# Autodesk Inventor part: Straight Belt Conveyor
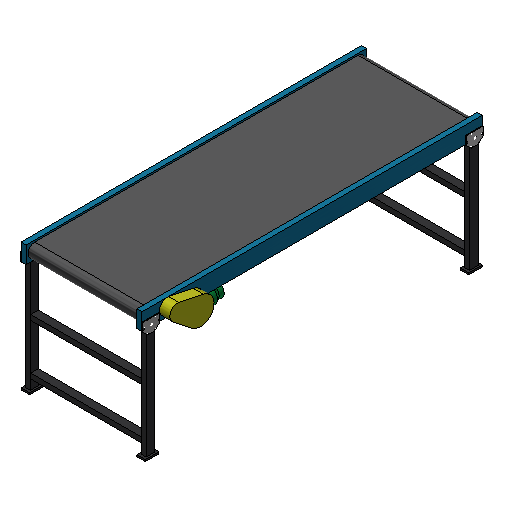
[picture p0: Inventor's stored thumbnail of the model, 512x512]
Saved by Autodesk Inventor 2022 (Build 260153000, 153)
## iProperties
ConnectorClass: Conveyor
family_type: normal
Created: 2009-10
Part Number: Straight Belt Conveyor
Document SubType Name: Modeling
Density: 1 g/cm^3
Material: 一般
Appearance: 既定
Key Parameters: Height=762.000 mm;Width=710.000 mm;Length=2000.000 mm;RollerDiameter=80.000 mm;NumberOfRungs=2.000 ul;FeetGap=1000.000 mm;MotorLocation="Front-Right";Legs="All"
Title: Straight Belt Conveyor
Author: Autodesk, Inc.
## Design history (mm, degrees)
sketch "Sketch1"
  geometry: L1 (662, 1000)-(662, -1000); L2 (662, -1000)-(762, -1000); L3 (762, -1000)-(762, 1000); L4 (762, 1000)-(662, 1000); L5 (712, 1000)-(0, 1000); L6 (712, -1000)-(0, -1000); L7 (0, -1000)-(0, 1000); L8 (0, -1387.4)-(0, 1387.4) reference; 2 further points
  constraints: 14 end point, 3 midpoint, 3 perpendicular, 2 coincident, 2 parallel, 1 collinear
  dimensions: "d110" = 100 distance between parallel lines of L1 L3 (= RailHeight); "d292" = 2000 distance of L6.end L5.end (derived); "d408" = 762 distance from line of L8 L3.end (derived); "d409" = 762 distance from line of L7 L2.end (derived)
extrude "Rail1" new body sketch "Sketch1" distance "d112" = 30 (= RailThickness); taper "d113" = 0 deg
node "MID"
mirror "Rail2"
sketch "Sketch8"
  geometry: L1 (-0.5, -25)-(-29.5, -25); L2 (-29.5, -25)-(-29.5, -75); L3 (-29.5, -75)-(-0.5, -75); L4 (-0.5, -75)-(-0.5, -25); L5 (-680, 0)-(-710, 0); L6 (-680.5, -25)-(-709.5, -25); L7 (-709.5, -25)-(-709.5, -75); L8 (-709.5, -75)-(-680.5, -75); L9 (-680.5, -75)-(-680.5, -25); L10 (-30, 0)-(0, 0); 4 further points
  constraints: 20 end point, 4 midpoint, 4 parallel, 3 perpendicular, 2 equal length, 2 horizontal, 2 vertical alignment
  dimensions: "d805" = 29 distance between parallel lines of L2 L4 (derived); "d806" = 50 distance between parallel lines of L3 L1; "d809" = 29 distance between parallel lines of L7 L9; "d810" = 50 distance between parallel lines of L6 L8 (derived); "d811" = 25 distance between parallel lines of L6 L5; "d812" = 25 distance between parallel lines of L1 L10 (derived)
extrude "Leg Mid 1" join sketch "Sketch8" distance "d731" = 662 (derived); taper "d732" = 0 deg
sketch "Sketch9"
  geometry: L1 (2.5, -565.8)-(47.5, -565.8); L2 (47.5, -565.8)-(47.5, -595.8); L3 (47.5, -595.8)-(2.5, -595.8); L4 (2.5, -595.8)-(2.5, -565.8); L5 (50, -662)-(0, -662) reference; 2 further points
  constraints: 8 end point, 2 midpoint, 2 parallel, 1 horizontal, 1 perpendicular, 1 vertical alignment
  dimensions: "d1060" = 30 distance of L3.end L1.start; "d1071" = 66.2 distance between parallel lines of L3 L5 (derived); "d1072" = 45 distance of L1.start L1.end
extrude "Rung Mid 1" join sketch "Sketch9" stored distance "d739" = 650 (derived); taper "d740" = 0 deg
node "ToCutBelow"
sketch "ToBeenCutOne"
  geometry: L1 (-30, 1000)-(-680, 1000); L2 (-355, 1000)-(-355, 400); L3 (-30, -1000)-(-680, -1000); L4 (-355, -1000)-(-355, 400); L5 (-284, 400)-(-426, 400); C1 r 35.5 at (-284, 400); C2 r 35.5 at (-426, 400); 1 further point
  constraints: 10 end point, 4 coincident, 4 perpendicular, 3 midpoint, 2 centre point, 1 horizontal
  dimensions: "d720" = 600 distance of L2.start L2.end (derived); "d756" = 142 distance of L5.start L5.end (derived); "d813" = 71 diameter of C1 (derived); "d814" = 71 diameter of C2 (derived)
extrude "ToBeenCutMid" join sketch "ToBeenCutOne" distance "d817" = 25 (derived); taper "d818" = 0 deg
sketch "Sketch10"
  geometry: L1 (-680, 100)-(-30, 100); L2 (-30, 100)-(-30, 0); L3 (-30, 0)-(-680, 0); L4 (-680, 0)-(-680, 100)
  constraints: 8 end point, 2 parallel, 1 horizontal, 1 perpendicular
extrude "Cut Mid" cut sketch "Sketch10" distance "d744" = 2000 (derived); taper "d745" = 0 deg
pattern_linear "Rung Mid 2" dims "d743" = 297.9 (derived)
sketch "Sketch11"
  geometry: L1 (-0.5, -25)-(-0.5, -75) reference; L2 (-29.5, -25)-(-0.5, -25) reference; L3 (-29.5, -75)-(-29.5, -25) reference; L4 (-0.5, -75)-(-29.5, -75) reference; L5 (-680.5, -25)-(-680.5, -75) reference; L6 (-709.5, -25)-(-680.5, -25) reference; L7 (-709.5, -75)-(-709.5, -25) reference; L8 (-680.5, -75)-(-709.5, -75) reference; L9 (10, -10)-(-40, -10); L10 (-40, -10)-(-40, -90); L11 (-40, -90)-(10, -90); L12 (10, -90)-(10, -10); L13 (-670, -10)-(-720, -10); L14 (-720, -10)-(-720, -90); L15 (-720, -90)-(-670, -90); L16 (-670, -90)-(-670, -10); 9 further points
  constraints: 16 end point, 8 midpoint, 4 parallel, 2 horizontal, 2 horizontal alignment, 2 perpendicular, 2 vertical alignment
  dimensions: "d1001" = 80 distance of L11.end L9.start; "d1002" = 50 distance of L10.end L11.end; "d1003" = 80 distance of L15.end L13.start; "d1004" = 50 distance of L14.end L15.end
extrude "LegBase" join sketch "Sketch11" distance "d1005" = 10.2 (derived); taper "d1006" = 0 deg
sketch "Sketch12"
  geometry: L1 (50, 0)-(0, 0) reference; L2 (-24, 47.55)-(74, 47.55); L3 (74, 47.55)-(74, -2.45); L4 (74, -2.45)-(45, -30); L5 (45, -30)-(5, -30); L6 (5, -30)-(-24, -2.45); L7 (-24, -2.45)-(-24, 47.55); L8 (0, -651.8)-(50, -651.8) reference; L9 (0, 0)-(50, 0) reference; 7 further points
  constraints: 12 end point, 5 midpoint, 4 vertical alignment, 3 equal length, 2 parallel, 2 perpendicular
  dimensions: "d1007" = 40 distance of L4.end L5.end; "d1008" = 98 distance of L2.start L2.end; "d1009" = 30 distance between parallel lines of L1 L5; "d1011" = 50 distance of L6.end L2.start
extrude "LegPan" join sketch "Sketch12" distance "d1012" = 5.1 (derived); taper "d1013" = 0 deg
mirror "LegPanE"
pattern_linear "Leg Mid 2"
pattern_linear "Leg Mid 3" dims "d1075" = 1900 (derived)
mirror "LegMid3"
mirror "LegMid4"
sketch "Sketch20"
  geometry: L1 (-950, 752)-(950, 752); L2 (-950, 672)-(950, 672); L3 (950, 752)-(950, 672); L4 (-950, 672)-(-950, 752); L5 (-950, 712)-(-950, 712); L6 (-1000, 662)-(-1000, 762) reference; L7 (1000, 762)-(1000, 662) reference; L8 (-950, 712)-(-1000, 712); L9 (950, 712)-(1000, 712); L10 (-1000, 762)-(-1000, 662) reference; L11 (1000, 662)-(1000, 762) reference; C1 r 40 at (-950, 712); A1 r 40 centre (950, 712) between (950, 752) and (950, 672)
  constraints: 14 end point, 4 midpoint, 4 tangent, 2 centre point, 2 equal length, 2 horizontal alignment, 2 point on circle
  dimensions: "d820" = 80 diameter of A1 (derived); "d831" = 80 diameter of C1 (derived); "d1000" = 0 distance of L5.start L5.end; "d1014" = 50 distance of L5.start L8.end (derived); "d1015" = 50 distance of L9.start L9.end (derived)
extrude "BeltMid" join sketch "Sketch20" distance "d821" = 650 (derived); taper "d822" = 0 deg
sketch "Sketch29"
  geometry: L1 (-1000, 662)-(-1000, 762) reference; L2 (1000, 762)-(1000, 662) reference; L3 (1000, 662)-(-1000, 662) reference; L4 (-1000, 762)-(1000, 762) reference; L5 (0, 762)-(0, 661); L6 (-75, 661)-(75, 661); L7 (-75, 761)-(75, 761); L8 (-75, 561)-(75, 561); A1 r 100 centre (-75, 661) between (-75, 761) and (-75, 561); A2 r 100 centre (75, 661) between (75, 561) and (75, 761)
  constraints: 8 end point, 4 point on circle, 4 tangent, 2 centre point, 2 coincident, 2 midpoint, 2 parallel, 1 perpendicular
  dimensions: "d1067" = 101 distance of L5.start L5.end; "d1068" = 150 distance of L6.start L6.end; "d1069" = 100 radius of A1
extrude "M2.1" join sketch "Sketch29" distance "d898" = 50; taper "d899" = 0 deg
sketch "Sketch30"
  geometry: L1 (-174.995, 660)-(174.995, 660); L2 (0, 650)-(80, 650); L3 (80, 650)-(80, 550); L4 (80, 550)-(0, 550); L5 (0, 550)-(0, 650); 2 further points
  constraints: 10 end point, 2 midpoint, 2 perpendicular, 1 horizontal, 1 parallel, 1 vertical alignment
  dimensions: "d900" = 100 distance of L4.end L2.start; "d901" = 80 distance of L3.end L4.end; "d1070" = 10 distance between parallel lines of L1 L2
extrude "M2.2" join sketch "Sketch30" distance "d902" = 100; taper "d903" = 0 deg
sketch "Sketch31"
  geometry: L1 (-100, 100)-(-100, 0) reference; L2 (0, 0)-(-100, 0) reference; L3 (0, 100)-(0, 9.125) reference; C1 r 50 at (-50, 50); 2 further points
  constraints: 3 tangent, 1 centre point
extrude "M2.3" join sketch "Sketch31" distance "d904" = 80; taper "d905" = 0 deg
sketch "Sketch32" dims "d907" = 100 (derived)
  geometry: C1 r 15 at (0, 0); 3 further points
  constraints: 1 centre point, 1 coincident, 1 horizontal alignment
  dimensions: "d906" = 30 diameter of C1
extrude "M2.4" join sketch "Sketch32" distance "d908" = 20; taper "d909" = 0 deg
sketch "Sketch33"
  geometry: C1 r 15 at (0, 0) reference; C2 r 40 at (0, 0); 1 further point
  constraints: 1 centre point, 1 coincident
  dimensions: "d910" = 80 diameter of C2
extrude "M2.5" join sketch "Sketch33" distance "d911" = 30; taper "d912" = 0 deg
sketch "Sketch34"
  geometry: L1 (1000, 762)-(1000, 662); L2 (1000, 762)-(1000, 662) reference; L3 (843.023, 761.096)-(700.095, 731.999); L4 (765.848, 590.993)-(880.009, 681.779); L5 (-1000, 662)-(1000, 662) reference; L6 (852, 717)-(716.054, 653.607); L7 (-1000, 762)-(1000, 762) reference; A1 r 45 centre (852, 717) between (880.009, 681.779) and (843.023, 761.096); A2 r 80 centre (716.054, 653.607) between (700.095, 731.999) and (765.848, 590.993)
  constraints: 8 end point, 5 tangent, 4 point on circle, 2 centre point, 1 vertical
  dimensions: "d913" = 90 diameter of A1; "d1078" = 150 distance of L6.start L6.end; "d1079" = 148 distance from line of L1 L6.start; "d1080" = 80 radius of A2; "d1081" = 25 deg angle of L5 L6
extrude "M1.1" join sketch "Sketch34" distance "d915" = 50; taper "d916" = 0 deg
sketch "Sketch35"
  geometry: L1 (-716.054, 651.607)-(-636.054, 651.607); L2 (-636.054, 651.607)-(-636.054, 551.607); L3 (-636.054, 551.607)-(-716.054, 551.607); L4 (-716.054, 551.607)-(-716.054, 651.607); A1 r 80 centre (-716.054, 651.607) between (-636.495, 660) and (-765.848, 588.993) reference; 1 further point
  constraints: 8 end point, 2 parallel, 1 horizontal, 1 perpendicular
  dimensions: "d917" = 100 distance of L3.end L1.start; "d1077" = 80 distance of L2.end L3.end
extrude "M1.2" join sketch "Sketch35" distance "d918" = 98; taper "d919" = 0 deg
sketch "Sketch36"
  geometry: L1 (-98, 100)-(-98, 0) reference; L2 (0, 0)-(-98, 0) reference; L3 (0, 0)-(0, 100) reference; C1 r 49 at (-49, 49); 1 further point
  constraints: 3 tangent, 1 centre point
extrude "M1.3" join sketch "Sketch36" distance "d920" = 80; taper "d921" = 0 deg
sketch "Sketch37"
  geometry: C1 r 49 at (0, 0) reference; C2 r 15 at (0, 0); 1 further point
  constraints: 1 centre point, 1 coincident
  dimensions: "d922" = 98 diameter of C1 (derived); "d923" = 30 diameter of C2
extrude "M1.4" join sketch "Sketch37" distance "d924" = 20; taper "d925" = 0 deg
sketch "Sketch38"
  geometry: C1 r 15 at (0, 0) reference; C2 r 40 at (0, 0); 1 further point
  constraints: 1 centre point, 1 coincident
  dimensions: "d926" = 80 diameter of C2
extrude "M1.5" join sketch "Sketch38" distance "d927" = 30; taper "d928" = 0 deg
sketch "Sketch39"
  geometry: L1 (-1000, 662)-(-1000, 762) reference; L2 (-843.023, 761.096)-(-700.095, 731.999); L3 (-880.009, 681.779)-(-765.848, 590.993); L4 (1000, 762)-(-1000, 762) reference; L5 (-1000, 662)-(1000, 662) reference; L6 (-852, 717)-(-716.054, 653.607); L7 (901, 662)-(999, 662) reference; A1 r 45 centre (-852, 717) between (-843.023, 761.096) and (-880.009, 681.779); A2 r 80 centre (-716.054, 653.607) between (-765.848, 590.993) and (-700.095, 731.999); A3 r 45 centre (-852, 717) between (-843.023, 761.096) and (-880.009, 681.779); 1 further point
  constraints: 6 end point, 6 point on circle, 4 tangent, 3 centre point, 1 coincident, 1 concentric
  dimensions: "d929" = 90 diameter of A1; "d932" = 160 diameter of A2; "d1082" = 148 distance from line of A1.centre L1; "d1083" = 150 distance of L6.start L6.end; "d1084" = 25 deg angle of L5 L6; "d1111" = 55 distance from line of L7 A1.centre
extrude "M3.1" join sketch "Sketch39" distance "d933" = 60 (derived); taper "d934" = 0 deg
sketch "Sketch40"
  geometry: L1 (716.054, 653.607)-(636.054, 653.607); L2 (636.054, 653.607)-(636.054, 553.607); L3 (636.054, 553.607)-(716.054, 553.607); L4 (716.054, 553.607)-(716.054, 653.607); 4 further points
  constraints: 8 end point, 2 parallel, 1 coincident, 1 horizontal, 1 perpendicular, 1 other
  dimensions: "d935" = 80 distance of L2.end L3.end; "d1085" = 100 distance of L1.end L2.end
extrude "M3.2" join sketch "Sketch40" distance "d936" = 98; taper "d937" = 0 deg
sketch "Sketch41"
  geometry: L1 (98, 0)-(98, 100) reference; L2 (0, 100)-(0, 0) reference; L3 (0, 0)-(98, 0) reference; C1 r 49 at (49, 49); 4 further points
  constraints: 3 tangent, 1 centre point
extrude "M3.3" join sketch "Sketch41" distance "d938" = 80; taper "d939" = 0 deg
sketch "Sketch42"
  geometry: C1 r 49 at (0, 0) reference; C2 r 15 at (0, 0); 1 further point
  constraints: 1 centre point, 1 coincident
  dimensions: "d940" = 30 diameter of C2; "d941" = 98 diameter of C1 (derived)
extrude "M3.4" join sketch "Sketch42" distance "d942" = 20; taper "d943" = 0 deg
sketch "Sketch43"
  geometry: C1 r 15 at (0, 0) reference; C2 r 40 at (0, 0); 1 further point
  constraints: 1 centre point, 1 coincident
  dimensions: "d944" = 80 diameter of C2
extrude "M3.5" join sketch "Sketch43" distance "d945" = 30; taper "d946" = 0 deg
sketch "Sketch44"
  geometry: L1 (-2000, 100)-(-2000, 0) reference; L2 (-1843.023, 99.096)-(-1700.095, 69.999); L3 (-1765.848, -71.007)-(-1880.009, 19.779); L4 (-1852, 55)-(-1716.054, -8.393); L5 (0, 0)-(-2000, 0) reference; L6 (-2000, 100)-(0, 100) reference; A1 r 45 centre (-1852, 55) between (-1843.023, 99.096) and (-1880.009, 19.779); A2 r 80 centre (-1716.054, -8.393) between (-1765.848, -71.007) and (-1700.095, 69.999); A3 r 45 centre (-1852, 55) between (-1843.023, 99.096) and (-1880.009, 19.779)
  constraints: 6 end point, 6 point on circle, 5 tangent, 3 centre point, 1 coincident
  dimensions: "d948" = 90 diameter of A1; "d949" = 160 diameter of A2; "d1086" = 150 distance of L4.start L4.end; "d1087" = 25 deg angle of L4 L5; "d1088" = 148 distance from line of A1.centre L1
extrude "M4.1" join sketch "Sketch44" distance "d950" = 60 (derived); taper "d951" = 0 deg
sketch "Sketch45"
  geometry: L1 (1716.054, -8.393)-(1636.054, -8.393); L2 (1636.054, -8.393)-(1636.054, -108.393); L3 (1636.054, -108.393)-(1716.054, -108.393); L4 (1716.054, -108.393)-(1716.054, -8.393); A1 r 80 centre (1716.054, -8.393) between (1636.495, 0) and (1765.848, -71.007) reference
  constraints: 8 end point, 2 parallel, 1 coincident, 1 horizontal, 1 perpendicular
  dimensions: "d952" = 100 distance of L3.end L1.start; "d1089" = 80 distance of L2.end L3.end
extrude "M4.2" join sketch "Sketch45" distance "d953" = 100; taper "d954" = 0 deg
sketch "Sketch46"
  geometry: L1 (100, 0)-(100, 100) reference; L2 (0, 100)-(0, 0) reference; L3 (0, 0)-(100, 0) reference; C1 r 50 at (50, 50); 3 further points
  constraints: 3 tangent, 1 centre point
extrude "M4.3" join sketch "Sketch46" distance "d955" = 80; taper "d956" = 0 deg
sketch "Sketch47"
  geometry: C1 r 50 at (0, 0) reference; C2 r 15 at (0, 0); 1 further point
  constraints: 1 centre point, 1 coincident
  dimensions: "d957" = 100 diameter of C1 (derived); "d958" = 30 diameter of C2
extrude "M4.4" join sketch "Sketch47" distance "d959" = 20; taper "d960" = 0 deg
sketch "Sketch48"
  geometry: C1 r 15 at (0, 0) reference; C2 r 40 at (0, 0); 1 further point
  constraints: 1 centre point, 1 coincident
  dimensions: "d961" = 80 diameter of C2
extrude "M4.5" join sketch "Sketch48" distance "d962" = 30; taper "d963" = 0 deg
sketch "Sketch49"
  geometry: L1 (-1075, 99)-(-925, 99); L2 (-925, -101)-(-1075, -101); L3 (-2000, 100)-(0, 100) reference; L4 (-1000, 100)-(-1000, -1); L5 (-1075, -1)-(-925, -1); A1 r 100 centre (-1075, -1) between (-1075, 99) and (-1075, -101); A2 r 100 centre (-925, -1) between (-925, -101) and (-925, 99)
  constraints: 8 end point, 4 point on circle, 4 tangent, 2 centre point, 2 coincident, 2 midpoint, 2 perpendicular, 1 equal radius, 1 parallel
  dimensions: "d964" = 200 diameter of A1; "d1090" = 101 distance of L4.start L4.end; "d1091" = 150 distance of L5.start L5.end
extrude "M5.1" join sketch "Sketch49" distance "d965" = 50; taper "d966" = 0 deg
sketch "Sketch50"
  geometry: L1 (920, -10)-(1000, -10); L2 (1000, -10)-(1000, -110); L3 (1000, -110)-(920, -110); L4 (920, -110)-(920, -10); L5 (1174.995, 0)-(825.005, 0) reference; 2 further points
  constraints: 8 end point, 2 midpoint, 2 parallel, 1 horizontal, 1 perpendicular, 1 vertical alignment
  dimensions: "d967" = 100 distance of L3.end L1.start; "d968" = 80 distance between parallel lines of L2 L4; "d1092" = 10 distance between parallel lines of L1 L5
extrude "M5.2" join sketch "Sketch50" distance "d969" = 98; taper "d970" = 0 deg
sketch "Sketch51"
  geometry: L1 (98, -9)-(98, 91) reference; L2 (0, -9)-(98, -9) reference; C1 r 49 at (49, 40); 2 further points
  constraints: 2 tangent, 1 centre point, 1 vertical alignment, 1 other
extrude "M5.3" join sketch "Sketch51" distance "d971" = 80; taper "d972" = 0 deg
sketch "Sketch52" dims "d974" = 98 (derived)
  geometry: C1 r 15 at (0, 0); 3 further points
  constraints: 1 centre point, 1 coincident, 1 horizontal alignment
  dimensions: "d973" = 30 diameter of C1
extrude "M5.4" join sketch "Sketch52" distance "d975" = 20; taper "d976" = 0 deg
sketch "Sketch53"
  geometry: C1 r 15 at (0, 0) reference; C2 r 40 at (0, 0); 1 further point
  constraints: 1 centre point, 1 coincident
  dimensions: "d977" = 80 diameter of C2
extrude "M5.5" join sketch "Sketch53" distance "d978" = 30; taper "d979" = 0 deg
sketch "Sketch54"
  geometry: L1 (0, 0)-(0, 100) reference; L2 (-156.977, 99.096)-(-299.905, 69.999); L3 (-119.991, 19.779)-(-234.152, -71.007); L4 (0, 0)-(-2000, 0) reference; L5 (-283.946, -8.393)-(-148, 55); A1 r 45 centre (-148, 55) between (-119.991, 19.779) and (-156.977, 99.096); A2 r 80 centre (-283.946, -8.393) between (-299.905, 69.999) and (-234.152, -71.007)
  constraints: 6 end point, 4 point on circle, 4 tangent, 2 centre point
  dimensions: "d981" = 90 diameter of A1; "d984" = 160 diameter of A2; "d1093" = 150 distance of L5.start L5.end; "d1094" = 25 deg angle of L4 L5; "d1095" = 148 distance from line of L5.end L1; "d1112" = 55 distance from line of L4 L5.end
extrude "M6.1" join sketch "Sketch54" distance "d982" = 50; taper "d983" = 0 deg
sketch "Sketch55"
  geometry: L1 (283.946, -8.393)-(363.946, -8.393); L2 (363.946, -8.393)-(363.946, -108.393); L3 (363.946, -108.393)-(283.946, -108.393); L4 (283.946, -108.393)-(283.946, -8.393); 3 further points
  constraints: 8 end point, 2 parallel, 1 coincident, 1 horizontal, 1 perpendicular, 1 other
  dimensions: "d985" = 100 distance of L3.end L1.start; "d986" = 80 distance of L2.end L3.end
extrude "M6.2" join sketch "Sketch55" distance "d987" = 98; taper "d988" = 0 deg
sketch "Sketch56"
  geometry: L1 (-98, 100)-(-98, 0) reference; L2 (0, 0)-(-98, 0) reference; L3 (0, 0)-(0, 100) reference; C1 r 49 at (-49, 49); 3 further points
  constraints: 3 tangent, 1 centre point
extrude "M6.3" join sketch "Sketch56" distance "d989" = 80; taper "d990" = 0 deg
sketch "Sketch57"
  geometry: C1 r 49 at (0, 0) reference; C2 r 15 at (0, 0); 1 further point
  constraints: 1 centre point, 1 coincident
  dimensions: "d991" = 30 diameter of C2
extrude "M6.4" join sketch "Sketch57" distance "d992" = 20; taper "d993" = 0 deg
sketch "Sketch58"
  geometry: C1 r 15 at (0, 0) reference; C2 r 40 at (0, 0); 1 further point
  constraints: 1 centre point, 1 coincident
  dimensions: "d994" = 80 diameter of C2
extrude "M6.5" join sketch "Sketch58" distance "d995" = 30; taper "d996" = 0 deg
node "Landing Surface_Work Plane1"
node "Landing Surface_Work Plane2"
workpoint "Work Point1"
  workplane "Work Plane22"
  workplane "Work Plane23"
node "Connector_Work Axis1"
node "Connector 1_Work Point1"
node "Connector 2_Work Point1"
node "Connector1"
node "Connector2"
workplane "Work Plane28"
node "Landing Surface"
node "Insertion Point1"
body "Solid5"
node "Projected Loop14"
node "Projected Loop15"
node "Projected Loop17"
node "Projected Loop18"
other parameters: "RailThickness" = 30 [user parameter; used in 1 equation term], "RailHeight" = 100 [user parameter; used in 1 equation term], "Thickness" = 10.2 [user parameter], "d162" = 355 (derived), "Height_q" = 762 [user parameter], "Location_" = 3 [user parameter], "Angle" = 45 deg [user parameter], "BranchLength" = 991 [user parameter], "d562" = 662 (derived), "RungDistance" = 297.9 [user parameter], "Location" = 3 [user parameter], "Length2_q" = 991 [user parameter], "Angle_q" = 45 deg [user parameter], "d1096" = -762 (derived), "d1113" = 355, "d1114" = 762, "d1116" = 90 deg, "d1117" = 0, "d1118" = 90 deg, "d1119" = 355, "d1120" = 762, "d1122" = 90 deg, "d1123" = 0, "d1124" = -90 deg, "d1125" = -762 (derived)
